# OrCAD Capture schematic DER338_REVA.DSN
size Custom
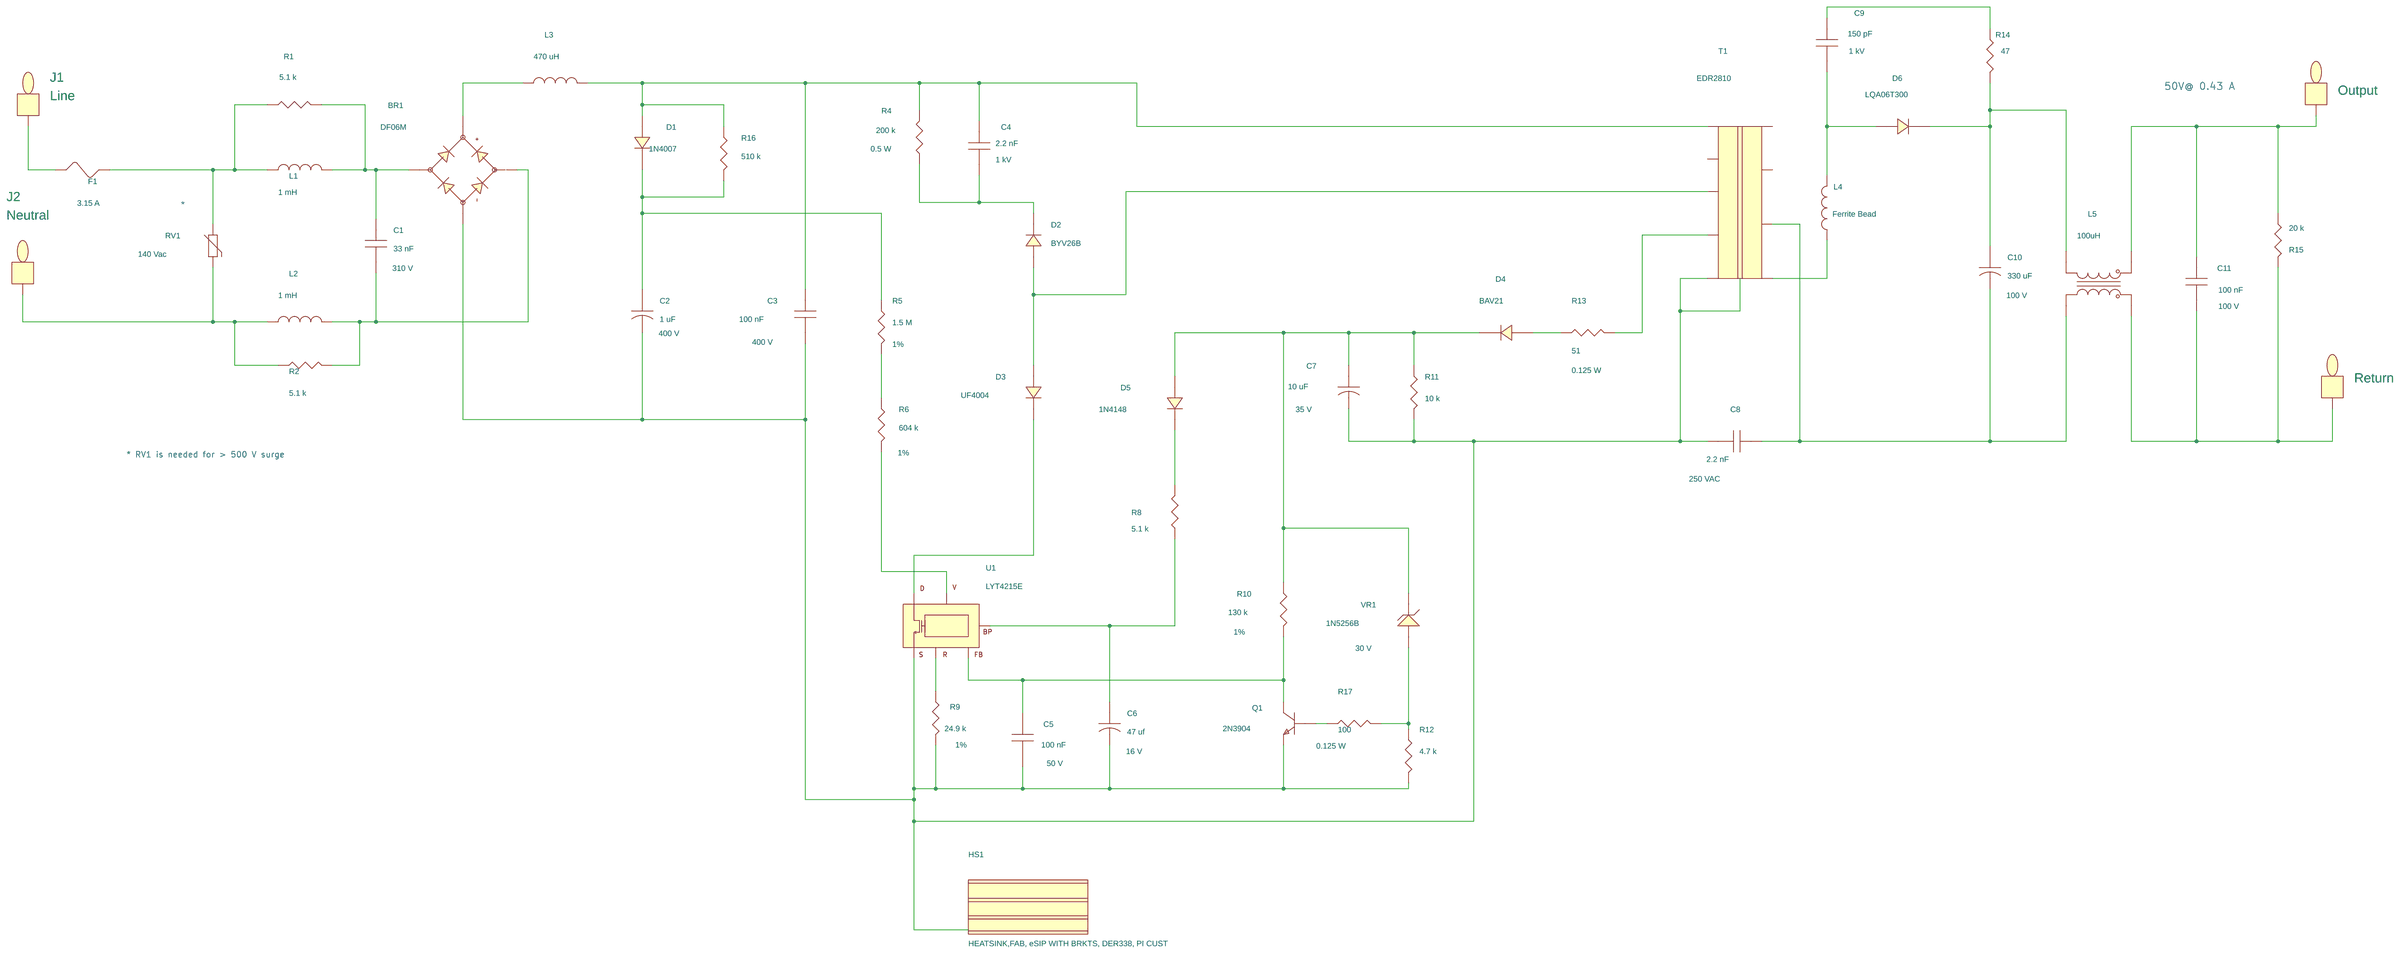
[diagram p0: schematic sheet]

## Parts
BR1  DF06M  [pidaxbridgedfm]
C1  33 nF  [pi_np_cap400x160ls300d040]
C2  1 uF  [pipolcapcyld250ls100030]
C3  100 nF  [pinpcaprad500x260400040]
C4  2.2 nF  [pinpcaprad290x160250030]
C5  100 nF  [pinpcaprad200x100200030]
C6  47 uf  [pipolcapclyd248ls098028]
C7  10 uF  [pipolcapclyd200ls80030]
C8  2.2 nF  [pinpycaprad540x290ls400040]
C9  150 pF  [pinpcaprad250x100200030]
C10  330 uF  [pipolcapclyd500ls2000401000lh]
C11  100 nF  [pinpcaprad200x100100030]
D1  1N4007  [pidv200x110x040do41]
D2  BYV26B  [pidax425x150040sod57]
D3  UF4004  [pidv200x110x040do41]
D4  BAV21  [pidv200x080x030do35]
D5  1N4148  [pidv200x080x030do35]
D6  LQA06T300  [PI_TO220]
F1  3.15 A  [pi_rst_microfuse]
HS1  HEATSINK,FAB, eSIP WITH BRKTS, DER338, PI CUST  [pi_hs_der338_esip]
J1  Line  [pitpkeystone125x125]
J2  Neutral  [pitpkeystone125x125]
L1  1 mH  [pichoke030dials200035]
L2  1 mH  [pichoke030dials200035]
L3  470 uH  [pi_choke_tok441ls197d043]
L4  Ferrite Bead  [pi12wvresd180ls150d040]
L5  100uH  [pi_toroid_cm_choke_4p]
Output  CON1  [pitpkeystone125x125]
Q1  2N3904  [PITO92R100]
R1  5.1 k  [pi18wvresd80ls100d030]
R2  5.1 k  [pi18wvresd80ls100d030]
R4  200 k  [pi12wvresd180ls150d040]
R5  1.5 M  [pi14wresd100ls500d030]
R6  604 k  [pi14wvresd100ls200d030]
R8  5.1 k  [pi14wvresd100ls100d030]
R9  24.9 k  [pi14wvresd100ls100d030]
R10  130 k  [pi14wvresd100ls100d030]
R11  10 k  [pi14wvresd100ls100d030]
R12  4.7 k  [pi18wvresd80ls100d030]
R13  51  [pi18wvresd80ls100d030]
R14  47  [pi14wvresd100ls100d030]
R15  20 k  [pi14wvresd100ls100d030]
R16  510 k  [pi14wvresd100ls100d030]
R17  100  [pi18wvresd80ls100d030]
Return  CON1  [pitpkeystone125x125]
RV1  140 Vac  [pidisc350x225ls240x140040]
T1  EDR2810  [pi_bobbin_edr2810_9p]
U1  LYT4215E  [piicesip76th]
VR1  1N5256B  [pidv200x080x030do35]

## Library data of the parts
BR1 = DIODE_BRIDGE_+-~~: Part Number: 15-00367-00
C1 = CAP_NP: Disp_Voltage: 310 V; Part Number: 20-01114-00; Voltage: 310 V
C2 = CAP_POL: ALT_SYMBOLS: pipolcapcyld250ls100030h; Disp_Voltage: 400 V; Part Number: 20-00800-00; Voltage: 400 V
C3 = CAP_NP: Disp_Voltage: 400 V; Part Number: 20-00368-00; Voltage: 400 V
C4 = CAP_NP: Disp_Voltage: 1 kV; Part Number: 20-00659-00; Voltage: 1 kV
C5 = CAP_NP: Disp_Voltage: 50 V; Part Number: 20-00536-00; Voltage: 50 V
C6 = CAP_POL: Disp_Voltage: 16 V; Part Number: 24-00011-00; Voltage: 16 V
C7 = CAP_POL: ALT_SYMBOLS: pipolcapclyd200ls80030h; Disp_Voltage: 35 V; FPLIST: pipolcapclyd200ls80030,pipolcapclyd200ls80030h; Part Number: 20-01007-00; Voltage: 35 V
C8 = CAP_NP: ALT_SYMBOLS: pinpycaprad540x290ls400040h; Disp_Voltage: 250 VAC; FPLIST: pinpycaprad540x290ls400040,pinpycaprad540x290ls400040h; Part Number: 20-00376-00; Voltage: 250 VAC
C9 = CAP_NP: Disp_Voltage: 1 kV; Part Number: 20-00353-00; Voltage: 1 kV
C10 = CAP_POL: Disp_Voltage: 100 V; FPLIST: pipolcapclyd500ls200040,pipolcapclyd500ls2000401000lh; Part Number: 20-01042-00; Voltage: 100 V
C11 = CAP_NP: Disp_Voltage: 100 V; Part Number: 20-00773-00; Voltage: 100 V
D1 = DIODE: ALT_SYMBOLS: pidax475x125040do41,pidv200x110x040do41wbead,pidax390x125040do41; COMPGROUP: 1; FPLIST: pidv200x110x040do41,pidax475x125040do41,pidv200x110x040do41wbead,pidax390x125040do41; Part Number: 15-00623-00
D2 = DIODE: FPLIST: pidv200x150x040sod57,pidax425x150040sod57; Part Number: 15-00127-00
D3 = DIODE: ALT_SYMBOLS: pidax475x125040do41,pidax390x125040do41; FPLIST: pidv200x110x040do41,pidax475x125040do41,pidax390x125040do41; Part Number: 15-00108-00
D4 = DIODE: ALT_SYMBOLS: pidax375x070030do35,pidv100x080x030do35; FPLIST: pidv200x080x030do35,pidax375x070030do35,pidv100x080x030do35; Part Number: 15-00084-00
D5 = DIODE: ALT_SYMBOLS: pidax375x070030do35,pidv100x080x030do35; FPLIST: pidv200x080x030do35,pidax375x070030do35,pidv100x080x030do35; Part Number: 15-00083-00
D6 = DIODE: FPLIST: pidvt0220acreva,PI_TO220; Part Number: 15-00837-00
F1 = FUSE: FPLIST: pi_rst_microfuse,pirstmicrofusehoz; Part Number: 40-00020-00
HS1 = HS-PI_CUSTOM: Part Number: 61-00109-01
J1 = TESTPOINT: Part Number: 35-00044-00
J2 Return = TESTPOINT: Part Number: 35-00042-00
L1 L2 = INDUCTOR: Part Number: 30-00165-00
L3 = INDUCTOR: Part Number: 30-00261-00
L4 = INDUCTOR: FPLIST: pi12wresd180ls675d040,pi12wvresd180ls150d040,pi12wvresd180ls200d040,pi12wvresd180ls250d040; Part Number: 30-00145-00
L5 = INDUCTOR_4P: Part Number: 32-00276-00
Output = TESTPOINT: Part Number: 35-00043-00
Q1 = NPN_EBC: ALT_SYMBOLS: PIT092100; FPLIST: PITO92R100,PIT092100; Part Number: 55-00001-00
R1 R2 = R: ALT_SYMBOLS: pi18wresd080ls300d030; Disp_Power: 0.125 W; FPLIST: pi18wvresd80ls100d030,pi18wresd080ls300d030; PCB Editor PCBFP: pismr0805; Part Number: 05-02354-00; Tol: 5%
R4 = R: ALT_SYMBOLS: pi12wvresd180ls200d040,pi12wvresd180ls250d040,pi12wresd180ls675d040; Disp_Power: 0.5 W; FPLIST: pi12wvresd180ls150d040,pi12wvresd180ls200d040,pi12wvresd180ls250d040,pi12wresd180ls675d040; Part Number: 05-02730-00
R5 = R: ALT_SYMBOLS: pi14wvresd100ls200d030,pi14wresd100ls400d030,pi14wresd100ls500d030; Disp_Tol: 1%; FPLIST: pi14wvresd100ls100d030,pi14wvresd100ls200d030,pi14wresd100ls400d030,pi14wresd100ls500d030; PCB Editor PCBFP: pismr1206; Part Number: 05-03524-00; Tol: 5%
R6 = R: ALT_SYMBOLS: pi14wvresd100ls200d030,pi14wresd100ls400d030,pi14wresd100ls500d030; Disp_Tol: 1%; FPLIST: pi14wvresd100ls100d030,pi14wvresd100ls200d030,pi14wresd100ls400d030,pi14wresd100ls500d030; Part Number: 05-02243-00
R8 = R: ALT_SYMBOLS: pi14wvresd100ls200d030,pi14wresd100ls400d030,pi14wresd100ls500d030; FPLIST: pi14wvresd100ls100d030,pi14wvresd100ls200d030,pi14wresd100ls400d030,pi14wresd100ls500d030; PCB Editor PCBFP: pismr1206; Part Number: 05-02524-00; Tol: 5%
R9 = R: ALT_SYMBOLS: pi14wvresd100ls200d030,pi14wresd100ls400d030,pi14wresd100ls500d030; Disp_Tol: 1%; FPLIST: pi14wvresd100ls100d030,pi14wvresd100ls200d030,pi14wresd100ls400d030,pi14wresd100ls500d030; PCB Editor PCBFP: pismr0805; Part Number: 05-02110-00; Tol: 1%
R10 = R: ALT_SYMBOLS: pi14wvresd100ls200d030,pi14wresd100ls400d030,pi14wresd100ls500d030; Disp_Tol: 1%; FPLIST: pi14wvresd100ls100d030,pi14wvresd100ls200d030,pi14wresd100ls400d030,pi14wresd100ls500d030; Part Number: 05-02179-00
R11 = R: ALT_SYMBOLS: pi14wvresd100ls200d030,pi14wresd100ls400d030,pi14wresd100ls500d030; FPLIST: pi14wvresd100ls100d030,pi14wvresd100ls200d030,pi14wresd100ls400d030,pi14wresd100ls500d030; PCB Editor PCBFP: pismr1206; Part Number: 05-02531-00; Tol: 5%
R12 = R: ALT_SYMBOLS: pi18wresd080ls300d030; Disp_Power: 0.125 W; FPLIST: pi18wvresd80ls100d030,pi18wresd080ls300d030; Part Number: 05-02353-00
R13 = R: ALT_SYMBOLS: pi18wresd080ls300d030; Disp_Power: 0.125 W; FPLIST: pi18wvresd80ls100d030,pi18wresd080ls300d030; Part Number: 05-02306-00
R14 = R: ALT_SYMBOLS: pi14wvresd100ls200d030,pi14wresd100ls400d030,pi14wresd100ls500d030; FPLIST: pi14wvresd100ls100d030,pi14wvresd100ls200d030,pi14wresd100ls400d030,pi14wresd100ls500d030; Part Number: 05-02475-00
R15 = R: ALT_SYMBOLS: pi14wvresd100ls200d030,pi14wresd100ls400d030,pi14wresd100ls500d030; FPLIST: pi14wvresd100ls100d030,pi14wvresd100ls200d030,pi14wresd100ls400d030,pi14wresd100ls500d030; PCB Editor PCBFP: pismr1206; Part Number: 05-02538-00; Tol: 5%
R16 = R: ALT_SYMBOLS: pi14wvresd100ls200d030,pi14wresd100ls400d030,pi14wresd100ls500d030; FPLIST: pi14wvresd100ls100d030,pi14wvresd100ls200d030,pi14wresd100ls400d030,pi14wresd100ls500d030; Part Number: 05-02572-00
R17 = R: ALT_SYMBOLS: pi18wresd080ls300d030; Disp_Power: 0.125 W; FPLIST: pi18wvresd80ls100d030,pi18wresd080ls300d030; Part Number: 05-02313-00
RV1 = VARISTOR: Part Number: 85-00001-00
T1 = BEDR2810_H_9P: Part Number: 25-00979-00
U1 = LNK40X_eSIP: Part Number: 10-00618-00
VR1 = DIODE_ZENER: ALT_SYMBOLS: pidax375x070030do35; Disp_Voltage: 30 V; FPLIST: pidv200x080x030do35,pidax375x070030do35; Part Number: 15-00047-00

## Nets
N1828072: J2.1 L2.1 R2.1 RV1.2
N2034514: R5.2 R6.2
N2034608: D3.1 U1.7(D)
N2034868: C5.1 Q1.3(COLLECTOR) R10.2 U1.3(FB)
N2034902: D2.2 D3.2 T1.3
N2034906: C2.1 D1.1 R5.1 R16.2
N2087372: BR1.3 C1.2 L2.2 R2.2
N2089046: C6.1 R8.2 U1.4(BP)
N2109142: F1.2 L1.1 R1.1 RV1.1
N2109297: BR1.4 C1.1 L1.2 R1.2
N2142347: BR1.2 C2.2 C3.2 C5.2 C6.2 C7.2 C8.2 HS1.1 Q1.1(EMITTER) R9.2 R11.1 R12.2 T1.5 U1.5(S)
N2216180: R13.1 T1.4
N2378865: F1.1 J1.1
N2448584: C7.1 D4.1 D5.2 R10.1 R11.2 VR1.1
N2451661: R9.1 U1.1(R)
N2492632: C10.1 D6.1 L5.1 R14.2
N2535639: C8.1 C10.2 L5.4 T1.7
N2539909: C11.1 L5.2 Output.1 R15.2
N2599685: D5.1 R8.1
N2869025: C3.1 C4.1 D1.2 L3.2 R4.2 R16.1 T1.1
N2871066: R6.1 U1.2(V)
N2889719: C4.2 D2.1 R4.1
N2895391: D4.2 R13.2
N2914407: BR1.1 L3.1
N2929446: R12.1 R17.1 VR1.2
N2934183: C11.2 L5.3 R15.1 Return.1
N2935852: C9.1 R14.1
N2971432: L4.1 T1.6
N2978816: C9.2 D6.2 L4.2
N2995553: Q1.2(BASE) R17.2

Not connected (* = marked no-connect by the designer): T1 2 8 9

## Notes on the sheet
- 50V@ 0.43 A
- *
- * RV1 is needed for > 500 V surge
